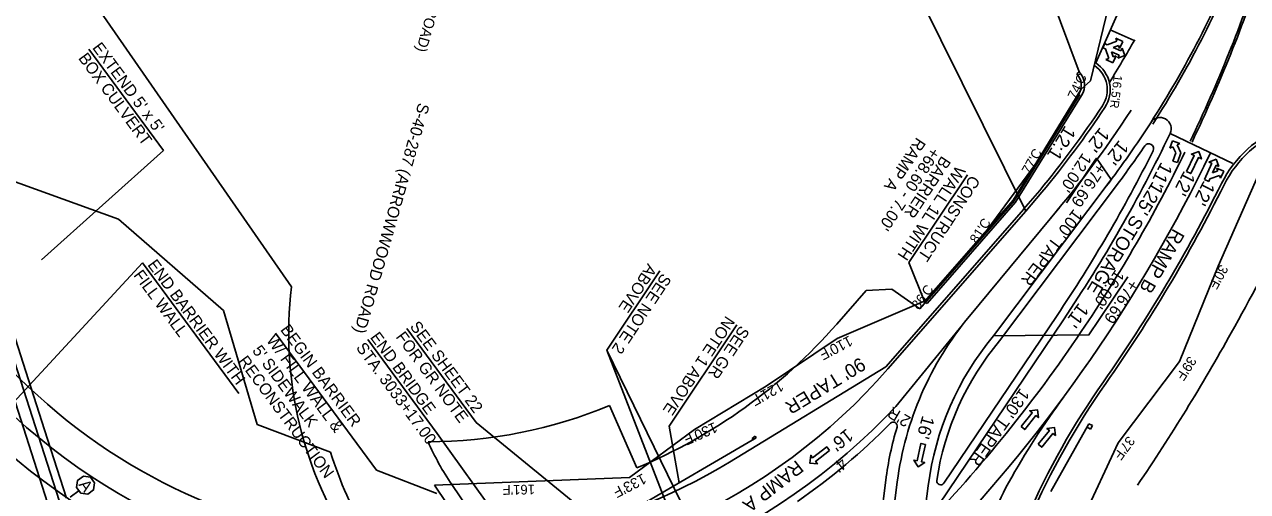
# Model space of a CAD drawing. Extents: x 1966090 to 1975830, y 788086 to 801233.
# Drawn here: x 1971145 to 1971774, y 796293 to 796534 of the extents above; entities that cross this region are included whole.
import ezdxf

# ---------------------------------------------------------------- set-up
doc = ezdxf.new("R2010")
doc.units = 0
for name, color, linetype in [('BR_PRESTRESSED BEAM', 7, 'Continuous'), ('BR_PROPOSED_DRAINAGE', 7, 'Continuous'), ('BR_PROPOSED_TRAVELWAY', 7, 'Continuous'), ('BR_REBAR', 7, 'Continuous'), ('RD_EX_Driveway_txCode', 7, 'Continuous'), ('RD_EX_RW_TX', 7, 'Continuous'), ('RD_EX_SU_Gas', 7, 'Continuous'), ('RD_EX_SU_H2O', 7, 'Continuous'), ('RD_EX_SU_SwpLmt', 7, 'Continuous'), ('RD_EX_Survey_Limits', 7, 'Continuous'), ('RD_EX_TX_Dam_ELEV', 7, 'Continuous'), ('RD_PD_PaveShd', 7, 'Continuous'), ('RD_PD_RW_TX', 7, 'Continuous'), ('RD_Sketch6', 7, 'Continuous'), ('RD_Sketch8', 7, 'Continuous')]:
    doc.layers.add(name, color=color, linetype=linetype)

msp = doc.modelspace()

# ---------------------------------------------------------------- linework, layer by layer
at = {"layer": 'BR_PRESTRESSED BEAM'}
for p, q in [((1971108.26, 796470.58), (1971155.03, 796325.07)), ((1971672.45, 796293.3), (1971692.03, 796328.19)), ((1971691.05, 796326.44), (1971692.03, 796328.19)), ((1971692.03, 796328.19), (1971693.77, 796327.21)), ((1971155.03, 796325.07), (1971166.35, 796289.84)), ((1971520.47, 796321.74), (1971518.87, 796320.52)), ((1971520.97, 796320.88), (1971520.47, 796321.74)), ((1971692.79, 796325.46), (1971691.05, 796326.44)), ((1971693.77, 796327.21), (1971692.79, 796325.46)), ((1971458.75, 796284.65), (1971520.97, 796320.88)), ((1971518.87, 796320.52), (1971519.25, 796319.87)), ((1971519.25, 796319.87), (1971520.97, 796320.88))]:
    msp.add_line(p, q, dxfattribs=at)
at = {"layer": 'BR_PROPOSED_DRAINAGE'}
for p, q in [((1971692.75, 796504.66), (1971704.88, 796554.82)), ((1971688.05, 796500.38), (1971692.75, 796504.66)), ((1971664.61, 796461.68), (1971688.05, 796500.38)), ((1971637.73, 796425.45), (1971664.61, 796461.68)), ((1971758.42, 796409.21), (1971779.3, 796456.76)), ((1971608.21, 796391.64), (1971637.73, 796425.45)), ((1971738.54, 796360.24), (1971758.42, 796409.21)), ((1971562.59, 796372.04), (1971608.21, 796391.64)), ((1971246.98, 796386.46), (1971264.31, 796327.75)), ((1971526.14, 796347.57), (1971562.59, 796372.04)), ((1971707.03, 796318.32), (1971738.54, 796360.24)), ((1971489.29, 796325.29), (1971526.14, 796347.57)), ((1971264.31, 796327.75), (1971302.09, 796313.64)), ((1971455.81, 796300.52), (1971489.29, 796325.29)), ((1971684.14, 796269.17), (1971707.03, 796318.32)), ((1971355.49, 796296.53), (1971455.81, 796300.52))]:
    msp.add_line(p, q, dxfattribs=at)
for points in [[(1971246.98, 796386.46), (1971192.99, 796433.53), (1971127.85, 796457)], [(1971355.49, 796296.53), (1971379.93, 796260.39), (1971397.2, 796235.33), (1971416.64, 796207.13), (1971494.67, 796095.38), (1971512.27, 796070.43)]]:
    msp.add_lwpolyline(points, dxfattribs=at)
msp.add_arc((1971482.81, 796369.08), 189.03, 197.05415, 211.48522, dxfattribs=at)
at = {"layer": 'BR_PROPOSED_TRAVELWAY'}
for p, q in [((1971706.7, 796451.43), (1971646.03, 796370.86)), ((1971706.7, 796451.43), (1971646.03, 796370.86)), ((1971685.67, 796423.58), (1971685.73, 796423.62)), ((1971617.41, 796297.63), (1971675.6, 796383.95)), ((1971617.41, 796297.63), (1971675.6, 796383.95)), ((1971582.1, 796256.96), (1971587.53, 796299.08)), ((1971582.1, 796256.96), (1971587.53, 796299.08))]:
    msp.add_line(p, q, dxfattribs=at)
for centre, radius, start, end in [((1971722.76, 796469.76), 2.5, 333.48209, 145.9867), ((1971722.76, 796469.76), 2.5, 333.48209, 145.9867), ((1971051.22, 796804.85), 753, 326.01649, 333.48209), ((1971051.22, 796804.85), 753, 326.01649, 333.48209), ((1971283.02, 796766.52), 528, 323.36189, 325.9867), ((1971283.02, 796766.52), 528, 323.36189, 325.9867), ((1971758.16, 796277.36), 146, 140.17527, 171.45647), ((1971758.16, 796277.36), 146, 140.17527, 171.45647), ((1971352.19, 796562.97), 334, 304.65236, 315.40271), ((1971352.19, 796562.97), 334, 304.65236, 315.40271), ((1971591.44, 796327.06), 2, 343.36017, 135.40271), ((1971591.44, 796327.06), 2, 343.36017, 135.40271), ((1971759.11, 796276.94), 173, 163.36017, 172.64958), ((1971759.11, 796276.94), 173, 163.36017, 172.64958), ((1971615.76, 796298.75), 2, 171.45647, 326.01649), ((1971615.76, 796298.75), 2, 171.45647, 326.01649)]:
    msp.add_arc(centre, radius, start, end, dxfattribs=at)
at = {"layer": 'BR_REBAR'}
for p, q in [((1971686.91, 796509.27), (1971685.74, 796508.14)), ((1971686.86, 796497.9), (1971653.01, 796443.16)), ((1971688.24, 796497.04), (1971654.32, 796442.19)), ((1971607.54, 796391.11), (1971653.01, 796443.16)), ((1971608.76, 796390.04), (1971654.32, 796442.19)), ((1971607.54, 796391.11), (1971608.76, 796390.04))]:
    msp.add_line(p, q, dxfattribs=at)
for radius in [8.37, 10]:
    msp.add_arc((1971679.74, 796502.3), radius, 328.26556, 44.16973, dxfattribs=at)
at = {"layer": 'RD_EX_Driveway_txCode'}
for p, q in [((1971700.16, 796523.81), (1971699.15, 796521.64)), ((1971701.46, 796523.22), (1971700.16, 796523.81)), ((1971706.38, 796525.03), (1971701.46, 796523.22)), ((1971704.52, 796521.79), (1971707.21, 796522.78)), ((1971709.45, 796524.88), (1971705.82, 796526.56)), ((1971705.82, 796526.56), (1971706.38, 796525.03)), ((1971707.21, 796522.78), (1971707.78, 796521.25)), ((1971707.78, 796521.25), (1971709.45, 796524.88)), ((1971699.15, 796521.64), (1971700.46, 796521.02)), ((1971700.46, 796521.02), (1971702.27, 796516.12)), ((1971702.27, 796516.12), (1971700.74, 796515.56)), ((1971704.52, 796516.95), (1971703.54, 796519.61)), ((1971703.54, 796519.61), (1971707.48, 796517.79)), ((1971704.38, 796513.88), (1971706.05, 796517.51)), ((1971708.48, 796519.97), (1971704.52, 796521.79)), ((1971706.05, 796517.51), (1971704.52, 796516.95)), ((1971707.48, 796517.79), (1971706.8, 796516.32)), ((1971706.8, 796516.32), (1971710.55, 796517.7)), ((1971709.17, 796521.45), (1971708.48, 796519.97)), ((1971710.55, 796517.7), (1971709.17, 796521.45)), ((1971700.74, 796515.56), (1971704.38, 796513.88)), ((1971733.67, 796469.91), (1971734.98, 796473.69)), ((1971734.98, 796473.69), (1971738.76, 796472.38)), ((1971738.76, 796472.38), (1971737.29, 796471.67)), ((1971735.13, 796470.62), (1971733.67, 796469.91)), ((1971736.66, 796467.5), (1971735.13, 796470.62)), ((1971735.23, 796463.37), (1971736.66, 796467.5)), ((1971737.29, 796471.67), (1971739.25, 796467.64)), ((1971739.25, 796467.64), (1971737.49, 796462.58)), ((1971737.49, 796462.58), (1971735.23, 796463.37)), ((1971751.39, 796453.82), (1971755.17, 796462.18)), ((1971753.68, 796462.85), (1971757.43, 796464.26)), ((1971755.17, 796462.18), (1971753.68, 796462.85)), ((1971757.36, 796461.19), (1971755.53, 796457.21)), ((1971758.84, 796460.52), (1971757.36, 796461.19)), ((1971757.43, 796464.26), (1971758.84, 796460.52)), ((1971758.23, 796458.23), (1971757.66, 796459.76)), ((1971757.66, 796459.76), (1971761.3, 796458.11)), ((1971753.58, 796452.83), (1971751.39, 796453.82)), ((1971754.19, 796454.14), (1971753.58, 796452.83)), ((1971759.08, 796455.99), (1971754.19, 796454.14)), ((1971755.53, 796457.21), (1971758.23, 796458.23)), ((1971759.65, 796454.47), (1971759.08, 796455.99)), ((1971761.3, 796458.11), (1971759.65, 796454.47))]:
    msp.add_line(p, q, dxfattribs=at)
for points in [[(1971742.22, 796457.91), (1971744.39, 796456.88), (1971748.34, 796465.16), (1971749.8, 796464.46), (1971748.47, 796468.23), (1971744.7, 796466.89), (1971746.17, 796466.19)], [(1971657.11, 796326.73), (1971658.98, 796325.23), (1971664.73, 796332.37), (1971666, 796331.35), (1971665.57, 796335.33), (1971661.59, 796334.9), (1971662.86, 796333.88)], [(1971665.91, 796317.6), (1971667.78, 796316.09), (1971673.53, 796323.24), (1971674.8, 796322.22), (1971674.37, 796326.19), (1971670.39, 796325.76), (1971671.66, 796324.74)], [(1971558.66, 796314.42), (1971557.18, 796316.31), (1971549.95, 796310.66), (1971548.95, 796311.94), (1971548.47, 796307.97), (1971552.44, 796307.49), (1971551.43, 796308.77)], [(1971607.99, 796317.53), (1971605.65, 796318.05), (1971603.63, 796309.11), (1971602.04, 796309.47), (1971604.18, 796306.08), (1971607.56, 796308.22), (1971605.97, 796308.58)]]:
    msp.add_lwpolyline(points, close=True, dxfattribs=at)
at = {"layer": 'RD_EX_SU_Gas'}
msp.add_line((1971733.78, 796477.5), (1971765.98, 796462.05), dxfattribs=at)
for centre, radius, start, end in [((1971283.02, 796766.52), 524, 327.25584, 338.20039), ((1971284.1, 796765.8), 524, 327.25584, 338.20039), ((1971051.22, 796804.85), 768, 334.44688, 341.82587), ((1971051.22, 796804.85), 769, 334.44688, 341.82587), ((1971283.02, 796766.52), 495, 327.94092, 330.89814), ((1971283.02, 796766.52), 512, 318.95532, 327.25584), ((1971051.22, 796804.85), 780, 316.30752, 334.3781), ((1971051.22, 796804.85), 768, 326.01649, 333.98154), ((1971051.22, 796804.85), 768, 316.30752, 326.01649), ((1972009.18, 796098.87), 410, 143.61171, 150.97037), ((1971790.59, 796220.19), 160, 150.97037, 166.99873)]:
    msp.add_arc(centre, radius, start, end, dxfattribs=at)
at = {"layer": 'RD_EX_Survey_Limits'}
msp.add_line((1971702.94, 796530.8), (1971715.3, 796525.35), dxfattribs=at)
at = {"layer": 'RD_EX_TX_Dam_ELEV'}
for p, q in [((1971102.57, 796657.26), (1971282.06, 796398.62)), ((1971687.39, 796497.57), (1971653.47, 796442.72)), ((1971605.05, 796387.31), (1971653.57, 796442.85)), ((1971562.32, 796379.42), (1971577.48, 796396.79)), ((1971590.65, 796397.42), (1971577.48, 796396.79)), ((1971605.05, 796387.31), (1971590.65, 796397.42)), ((1971445.56, 796337.54), (1971459.61, 796305.48))]:
    msp.add_line(p, q, dxfattribs=at)
msp.add_lwpolyline([(1971405.27, 796236.53), (1971364.41, 796296.88)], dxfattribs=at)
for centre, radius, start, end in [((1970655.54, 796992.68), 1270, 330.89814, 333.61821), ((1971479.12, 796374.54), 198.53, 173.03448, 214.09728), ((1971352.19, 796562.97), 279, 292.64542, 318.86295), ((1970830.29, 796895.41), 1070, 325.96474, 330.89814), ((1971352.19, 796562.97), 244, 270.00885, 292.49811), ((1971479.12, 796374.54), 138.53, 203.65221, 214.09728)]:
    msp.add_arc(centre, radius, start, end, dxfattribs=at)
at = {"layer": 'RD_PD_PaveShd'}
msp.add_line((1971104.45, 796469.35), (1971162.54, 796288.62), dxfattribs=at)
at = {"layer": 'RD_PD_RW_TX'}
for p, q in [((1971666.7, 796448.25), (1971658.45, 796438.56)), ((1971587.55, 796357.39), (1971658.46, 796438.57)), ((1971507.19, 796308.45), (1971587.55, 796357.39))]:
    msp.add_line(p, q, dxfattribs=at)
for centre, radius, start, end in [((1971686.46, 796500.04), 15, 326.55514, 55.93916), ((1971283.02, 796766.52), 498.5, 320.32196, 326.55514), ((1971813.84, 796424.98), 58.5, 69.26451, 153.52193), ((1971051.22, 796804.85), 793.5, 324.93367, 333.52193), ((1971352.19, 796562.97), 298, 221.21202, 301.34068), ((1972026.85, 796120.01), 398.5, 144.93367, 167.91315)]:
    msp.add_arc(centre, radius, start, end, dxfattribs=at)
at = {"layer": 'RD_Sketch6'}
for p, q in [((1971532.15, 796694.61), (1971659.59, 796437.59)), ((1971686.91, 796509.27), (1971645.1, 796621.56)), ((1971216.24, 796468.71), (1971177.73, 796520.95)), ((1971216.24, 796468.71), (1971153.4, 796412.49)), ((1971680.45, 796441.82), (1971695.11, 796463.7)), ((1971599.45, 796411.15), (1971629.61, 796456.2)), ((1971119.45, 796318.1), (1971205.42, 796410.94)), ((1971254.94, 796343.78), (1971205.42, 796410.94)), ((1971607.54, 796391.11), (1971599.45, 796411.15)), ((1971697.32, 796381.82), (1971711.98, 796403.71)), ((1971476.13, 796327.03), (1971510.95, 796379.03)), ((1971273.7, 796374.76), (1971325.67, 796304.26)), ((1971321.22, 796371.56), (1971356.87, 796323.19)), ((1971341.34, 796377.28), (1971376.99, 796328.91)), ((1971500.77, 796219.91), (1971444.18, 796366.06)), ((1971376.99, 796328.91), (1971438.42, 796278.68)), ((1971356.87, 796323.19), (1971406.64, 796253.73)), ((1971476.13, 796327.03), (1971481.38, 796297.83)), ((1971356.73, 796292.22), (1971325.67, 796304.26)), ((1971172.75, 796293.78), (1971168.26, 796290.45))]:
    msp.add_line(p, q, dxfattribs=at)
for points in [[(1971695.11, 796463.7), (1971695.83, 796464.79), (1971703.5, 796453.83)], [(1971471.47, 796406.81), (1971444.18, 796366.06), (1971503.03, 796245.08)], [(1971697.32, 796381.82), (1971692.01, 796373.89), (1971642.9, 796373.35)]]:
    msp.add_lwpolyline(points, dxfattribs=at)
msp.add_lwpolyline([(1971177.31, 796291.96), (1971180.25, 796294.14), (1971180.79, 796297.75), (1971178.61, 796300.69), (1971175, 796301.23), (1971172.06, 796299.06), (1971171.52, 796295.44), (1971173.69, 796292.5)], close=True, dxfattribs=at)
at = {"layer": 'RD_Sketch8'}
for p, q in [((1971710.41, 796547.73), (1971695.48, 796513.86)), ((1971098.74, 796467.52), (1971168.6, 796250.18)), ((1971703.5, 796453.83), (1971642.9, 796373.35)), ((1971667.85, 796447.28), (1971659.59, 796437.59)), ((1971588.67, 796356.4), (1971659.59, 796437.59)), ((1971630.58, 796383.57), (1971677.08, 796439.62)), ((1971626.96, 796379.05), (1971592.79, 796337.11)), ((1971678.92, 796381.72), (1971606.52, 796274.32)), ((1971587.97, 796255.56), (1971593.49, 796298.31)), ((1971606.52, 796274.32), (1971609.35, 796296.26))]:
    msp.add_line(p, q, dxfattribs=at)
for centre, radius, start, end in [((1971686.46, 796500.04), 16.5, 326.55514, 56.88198), ((1971283.02, 796766.52), 500, 320.32196, 326.55514), ((1971728.59, 796479.98), 5.75, 334.3781, 147.25584), ((1971813.84, 796424.98), 60, 69.26451, 153.52193), ((1971283.02, 796766.52), 524, 322.91379, 327.25584), ((1971051.22, 796804.85), 757, 326.01649, 334.3781), ((1971051.22, 796804.85), 792, 324.93367, 333.52193), ((1971759.11, 796276.94), 167, 140.32196, 172.64958), ((1971759.11, 796276.94), 151, 140.32196, 172.64958), ((1971352.19, 796562.97), 314, 221.21202, 318.86296), ((1972026.85, 796120.01), 400, 144.93367, 167.91315), ((1971352.19, 796562.97), 330, 221.21202, 316.81039)]:
    msp.add_arc(centre, radius, start, end, dxfattribs=at)

# ---------------------------------------------------------------- texts
at = {"layer": 'RD_EX_Driveway_txCode'}
for s, height, rotation, p in [('12:1', 7, 238.26556, (1971679.79, 796482.04)), ("12'", 7, 231.74315, (1971697.8, 796481.07)), ("12'", 7, 231.74315, (1971707.62, 796474.54)), ("11'", 7, 242.43003, (1971729.24, 796463.24)), ("12'", 7, 242.43003, (1971740.96, 796458.72)), ("125' STORAGE", 7, 238.73504, (1971724.88, 796453.24)), ("12'", 7, 242.43003, (1971751.1, 796453.65)), ("100' TAPER", 6.3, 233.23285, (1971684.3, 796439.11)), ("11'", 7, 233.83231, (1971686.89, 796390.8)), ("90' TAPER", 7, 211.44735, (1971574.39, 796362.67)), ("130' TAPER", 6.3, 234.68391, (1971656.81, 796346.92)), ("2'R", 6, 149.38144, (1971600.89, 796331.25)), ("16'", 6.667, 254.3144, (1971606.43, 796332.73)), ("16'", 6.667, 218.34916, (1971567.5, 796326.03)), ('RAMP A', 7, 218.06064, (1971541.66, 796309.8)), ("4'", 6, 219.2759, (1971564.52, 796311.12))]:
    msp.add_text(s, height=height, rotation=rotation, dxfattribs=at).set_placement(p)
at = {"layer": 'RD_EX_RW_TX'}
for s, rotation, p in [("74'C", 64.44821, (1971685.29, 796494.61)), ("77'C", 60.7754, (1971661.49, 796456.09)), ("81'C", 57.10259, (1971634.51, 796420.48)), ("30'F", 240.7754, (1971759.59, 796410.51)), ("86'C", 53.42979, (1971604.39, 796386.49)), ("39'F", 237.10259, (1971743.5, 796363.33)), ("37'F", 233.42979, (1971712.09, 796322.22)), ("161'F", 180.96689, (1971407.11, 796296.87))]:
    msp.add_text(s, height=5, rotation=rotation, dxfattribs=at).set_placement(p)
at = {"layer": 'RD_EX_SU_H2O'}
for s, height, rotation, p in [('(ARROWWOOD ROAD)', 5.3996, 254.2312, (1971367.31, 796595.95)), ('S-40-287 (ARROWWOOD ROAD)', 5.9996, 254.2312, (1971347.3, 796493.62)), ('RAMP B', 7, 240.33928, (1971735.47, 796429.02))]:
    msp.add_text(s, height=height, rotation=rotation, dxfattribs=at).set_placement(p)
at = {"layer": 'RD_EX_SU_SwpLmt'}
for s, rotation, p in [("110'F", 207.37873, (1971568.73, 796373.7)), ("121'F", 209.5172, (1971533.08, 796350.51)), ("130'F", 203.96323, (1971499.46, 796329.17)), ("133'F", 207.29152, (1971462.66, 796302.79))]:
    msp.add_text(s, height=5.4, rotation=rotation, dxfattribs=at).set_placement(p)
at = {"layer": 'RD_Sketch6'}
for s, height, rotation, p in [("EXTEND 5' x 5'", 5.9996, 306.55916, (1971179.35, 796521.6)), ('BOX CULVERT', 5.9996, 306.55916, (1971172.12, 796516.24)), ("16.5'R", 4.5, 263.21032, (1971704.8, 796507.78)), ('RAMP A', 6, 236.19133, (1971603.49, 796475.89)), ("+68.60 - 7.00'", 5.9996, 236.19133, (1971610.97, 796470.88)), ('BARRIER', 6, 236.71509, (1971616.39, 796466.35)), ("12.00'", 6, 236.19133, (1971688.88, 796467.87)), ('WALL 1L WITH', 5.9996, 236.71509, (1971623.91, 796461.42)), ('+76.69', 6, 236.19133, (1971696.35, 796462.87)), ('CONSTRUCT', 6, 236.71509, (1971631.44, 796456.48)), ('END BARRIER WITH ', 5.9996, 306.55744, (1971207.73, 796409.92)), ('ABOVE', 6, 236.21793, (1971465.23, 796410.98)), ('FILL WALL', 6, 306.55744, (1971200.5, 796404.56)), ('SEE NOTE 2', 6, 236.21793, (1971472.71, 796405.98)), ("16.00'", 6, 236.19133, (1971705.75, 796407.88)), ('+76.69', 6, 236.19133, (1971713.22, 796402.87)), ('BEGIN BARRIER', 5.9996, 306.55744, (1971276.01, 796376.49)), ('SEE SHEET 22', 5.9996, 306.55744, (1971342.59, 796378.19)), ('NOTE 1 ABOVE', 5.9996, 236.21793, (1971505.38, 796384.1)), ('SEE GR ', 6, 236.21793, (1971512.86, 796379.1)), ('W/ FILL WALL &', 5.9996, 306.55744, (1971268.78, 796371.13)), ('END BRIDGE', 6, 306.42425, (1971322.17, 796372.6)), ('FOR GR NOTE', 5.9996, 306.55744, (1971335.36, 796372.83)), ("5' SIDEWALK", 5.9996, 306.55744, (1971261.55, 796365.77)), ('STA. 3033+17.00', 5.9996, 306.42425, (1971314.93, 796367.25)), ('RECONSTRUCTION', 5.9996, 306.55744, (1971254.33, 796360.41)), ('A', 6, 306.50544, (1971172.29, 796296.77))]:
    msp.add_text(s, height=height, rotation=rotation, dxfattribs=at).set_placement(p)

doc.saveas('drawing.dxf')
